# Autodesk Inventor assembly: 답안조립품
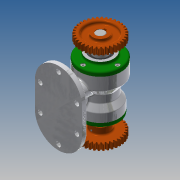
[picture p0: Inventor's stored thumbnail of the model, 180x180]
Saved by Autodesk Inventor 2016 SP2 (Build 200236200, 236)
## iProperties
Created: 2020-01
Part Number: 답안조립품
Document SubType Name: Assembly
Designer: EZ
Author: EZ
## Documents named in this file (13)
- C:\Users\EZ\Desktop\700104V1007\답안조립품.iam
- C:\Users\EZ\Desktop\700104V1007\본체.ipt
- C:\Users\EZ\Desktop\700104V1007\뒤커버.ipt
- C:\Users\EZ\Desktop\700104V1007\멈춤나사 M3.ipt
- C:\Users\EZ\Desktop\700104V1007\베어링 6203.ipt
- C:\Users\EZ\Desktop\700104V1007\베어링 6205.ipt
- C:\Users\EZ\Desktop\700104V1007\볼트 M4.ipt
- C:\Users\EZ\Desktop\700104V1007\스퍼기어.ipt
- C:\Users\EZ\Desktop\700104V1007\앞커버.ipt
- C:\Users\EZ\Desktop\700104V1007\오일 실 17 30 8.ipt
- C:\Users\EZ\Desktop\700104V1007\오일 실 25 38 8.ipt
- C:\Users\EZ\Desktop\700104V1007\축.ipt
- C:\Users\EZ\Desktop\700104V1007\키 5 x 5 x 18.ipt
